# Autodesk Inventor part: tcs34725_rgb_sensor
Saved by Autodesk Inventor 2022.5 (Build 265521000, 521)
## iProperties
Created: 2024-12
Part Number: tcs34725_rgb_sensor
Material: Generic
Document SubType Name: Modeling
Designer: AdminForWorker
Density: 1 g/cm^3
Appearance: Default
Title: tcs34725_rgb_sensor v1
Author: AdminForWorker
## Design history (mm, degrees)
feature "Body1"
body "Solid1"
